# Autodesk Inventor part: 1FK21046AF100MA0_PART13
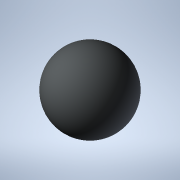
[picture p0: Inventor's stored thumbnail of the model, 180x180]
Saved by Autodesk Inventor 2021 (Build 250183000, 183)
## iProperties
Created: 2025-04
Part Number: 1FK21046AF100MA0_PART13
Material: Generic
Catalog Web Link: www.3dfindit.com
Description: -Servo synchronous motor
Document SubType Name: Modeling
Designer: psAdmin
Mass: 0.137258 g
Surface Area: 1.2868 cm^2
Volume: 0.137258 cm^3
Density: 1 g/cm^3
Appearance: PSOLRGB-212-217-219
Category: PARTsolutions
Title: 1FK21046AF100MA0_PART13
Author: Cadenas PARTsolutions
Comments: Servo synchronous motor
Sending System: PARTsolutions
Preprocessor: ST-DEVELOPER v19.3
PSOL_IDENT_0: {$CADENAS_DATA/23d-libs/siemens_ag/_cat_/4f/2b/1fk21046af100ma0.prj},216 {VTYP=3D},{NB=1FK21046AF100
PSOL_IDENT_1: MA0_PART13},{LINA=1FK21046AF100MA0_PART13},{NN=1FK21046AF100MA0_PART13},{NOPRJ=TRUE},{DATE=19.08.202
PSOL_IDENT_2: 5 14:00:37},{GEOMDATE=30.07.2025 02:01:06},{VERSION=},{LINEID=10},{WBVAR=},{WBNUMERIC=}  {NB=1FK2104
PSOL_IDENT_3: 6AF100MA0_PART13},{LINA=1FK21046AF100MA0_PART13},{KT=DUMMY},{PREVIEW=../../../_pool_/cb/72/p_d211_xx
PSOL_IDENT_4: _00434j.png},{DESCSHORT=SIMOTICS S-1FK2 HD, SINAMICS S210 3AC 400V-480V, 3.2 Nm, 3000 rpm},{DESCLONG=
PSOL_IDENT_5: SIMOTICS S-1FK2 HD servo motor M0=3.2 Nm; PN = 1 kW at nN=3000 rpm (380-480 V); PN = 0.5 kW at nN=15
PSOL_IDENT_6: 00 rpm (200-240 V); with holding brake; degree of protection IP64; cylindrical shaft D19x40mm; absol
PSOL_IDENT_7: ute encoder 22-bit + 12-bit multiturn (encoder AM22DQC); with OCC interface; plug size M17, rotatabl
PSOL_IDENT_8: e; SIMOTICS S-1FK2 servomotorfor a wide range of uses in industrial environments. SIMOTICS S‑1FK2 se
PSOL_IDENT_9: rvomotors are compact synchronous motors with a high dynamic performance that set themselves apart a
PSOL_IDENT_10: s a result of their high power density, degree of protection and overload capability. The motors are
PSOL_IDENT_11: available in two variants: as High Dynamic variant (highest dynamic performance as a result of the
PSOL_IDENT_12: low intrinsic moment of inertia for applications demanding a high dynamic performance with low moved
PSOL_IDENT_13: masses) - and as Compact variant (precise and stable closed-loop control for medium up to large mov
PSOL_IDENT_14: ed masses as a result of a medium intrinsic moment of inertia). SIMOTICSS‑1FK2 servomotors fully exp
PSOL_IDENT_15: loit their strengths in a system with the SINAMICSS210 frequency converter and simple connection usi
PSOL_IDENT_16: ng the one cable connection (OCC). Advantages include the short control and positioning times, fast
PSOL_IDENT_17: and precise correction of disturbing quantities as well as stable control with a high dynamic perfor
PSOL_IDENT_18: mance. The servo motors can be configured to address a wide range of requirements. For example with
PSOL_IDENT_19: and without holding brake, IP64 or IP65 degree of protection, singleturn or multiturn absolute encod
PSOL_IDENT_20: ers - to name just a few. Further, the servomotors are available in different shaft heights extendin
PSOL_IDENT_21: g from 20 to 100. A shaft sealing ring is available to achieve an IP65 degree of protection and for
PSOL_IDENT_22: subsequent mounting at the motor or as spare part. SIMOTICS - the optimum motor for each and every m
PSOL_IDENT_23: otion control application.},{INTNO=195125049673},{SUPPLIERALTNO=1FK2104-6AF10-0MA0},{MANUID=1FK21046
PSOL_IDENT_24: AF100MA0},{MANUNAME=Siemens},{MANUTYPEDESC=Synchronous motor 1FK2-HD 3.2 NM},{AAU732=SIMOTICS},{AAO0
PSOL_IDENT_25: 57=S-1FK2},{AAU734=SIMOTICS S-1FK2 HD servo motor M0=3.2 Nm; PN = 1 kW at nN=3000 rpm (380-480 V); P
PSOL_IDENT_26: N = 0.5 kW at nN=1500 rpm (200-240 V); with holding brake; degree of protection IP64; cylindrical sh
PSOL_IDENT_27: aft D19x40mm; absolute encoder 22-bit + 12-bit multiturn (encoder AM22DQC); with OCC interface; plug
PSOL_IDENT_28: size M17, rotatable;},{AAW338=Synchronous motor 1FK2-HD 3.2 NM},{AAO742=SIMOTICS},{AAO663=404294869
PSOL_IDENT_29: 4534},{NOCUPEROU=1},{PRICEQUANTITY=1},{QUANTITYMIN=1},{QUANTITYINT=1},{CTN=85015220},{COO=DE},{AAO67
PSOL_IDENT_30: 6=1FK2104-6AF10-0MA0},{AAO677=Siemens AG},{ORDERUNIT=C62},{CONTENTUNIT=C62}
NB: 1FK21046AF100MA0_PART13
NT: Servo synchronous motor
NBSYN: $MANUID._PART13
LINA: 1FK21046AF100MA0_PART13
CATALOG: SIEMENS
PREVIEW: ../../../_pool_/cb/72/p_d211_xx_00434j.png
DESCSHORT: SIMOTICS S-1FK2 HD, SINAMICS S210 3AC 400V-480V, 3.2 Nm, 3000 rpm
DESCLONG: SIMOTICS S-1FK2 HD servo motor M0=3.2 Nm; PN = 1 kW at nN=3000 rpm (380-480 V); PN = 0.5 kW at nN=1500 rpm (200-240 V); with holding brake; degree of protection
INTNO: 195125049673
SUPPLIERALTNO: 1FK2104-6AF10-0MA0
MANUID: 1FK21046AF100MA0
MANUNAME: Siemens
MANUTYPEDESC: Synchronous motor 1FK2-HD 3.2 NM
AAU732: SIMOTICS
AAO057: S-1FK2
AAU734: SIMOTICS S-1FK2 HD servo motor M0=3.2 Nm; PN = 1 kW at nN=3000 rpm (380-480 V); PN = 0.5 kW at nN=1500 rpm (200-240 V); with holding brake; degree of protection
AAW338: Synchronous motor 1FK2-HD 3.2 NM
AAO742: SIMOTICS
AAO663: 4042948694534.0
NOCUPEROU: 1
PRICEQUANTITY: 1
QUANTITYMIN: 1
QUANTITYINT: 1
CTN: 85015220
COO: DE
ARTICLENO: 1FK21046AF100MA0_PART13
BOMINFO: 1FK21046AF100MA0_PART13
CREATOR: CADENAS GmbH
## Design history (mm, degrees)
feature "2025_04_17_14_59_39_0177"
body "Solid1"
